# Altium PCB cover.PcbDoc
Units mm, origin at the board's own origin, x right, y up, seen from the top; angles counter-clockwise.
Board outline 100 x 100 mm, 2 copper layers (Top Layer, Bottom Layer); 4 components, 1 nets, 4 pads, 64 vias.
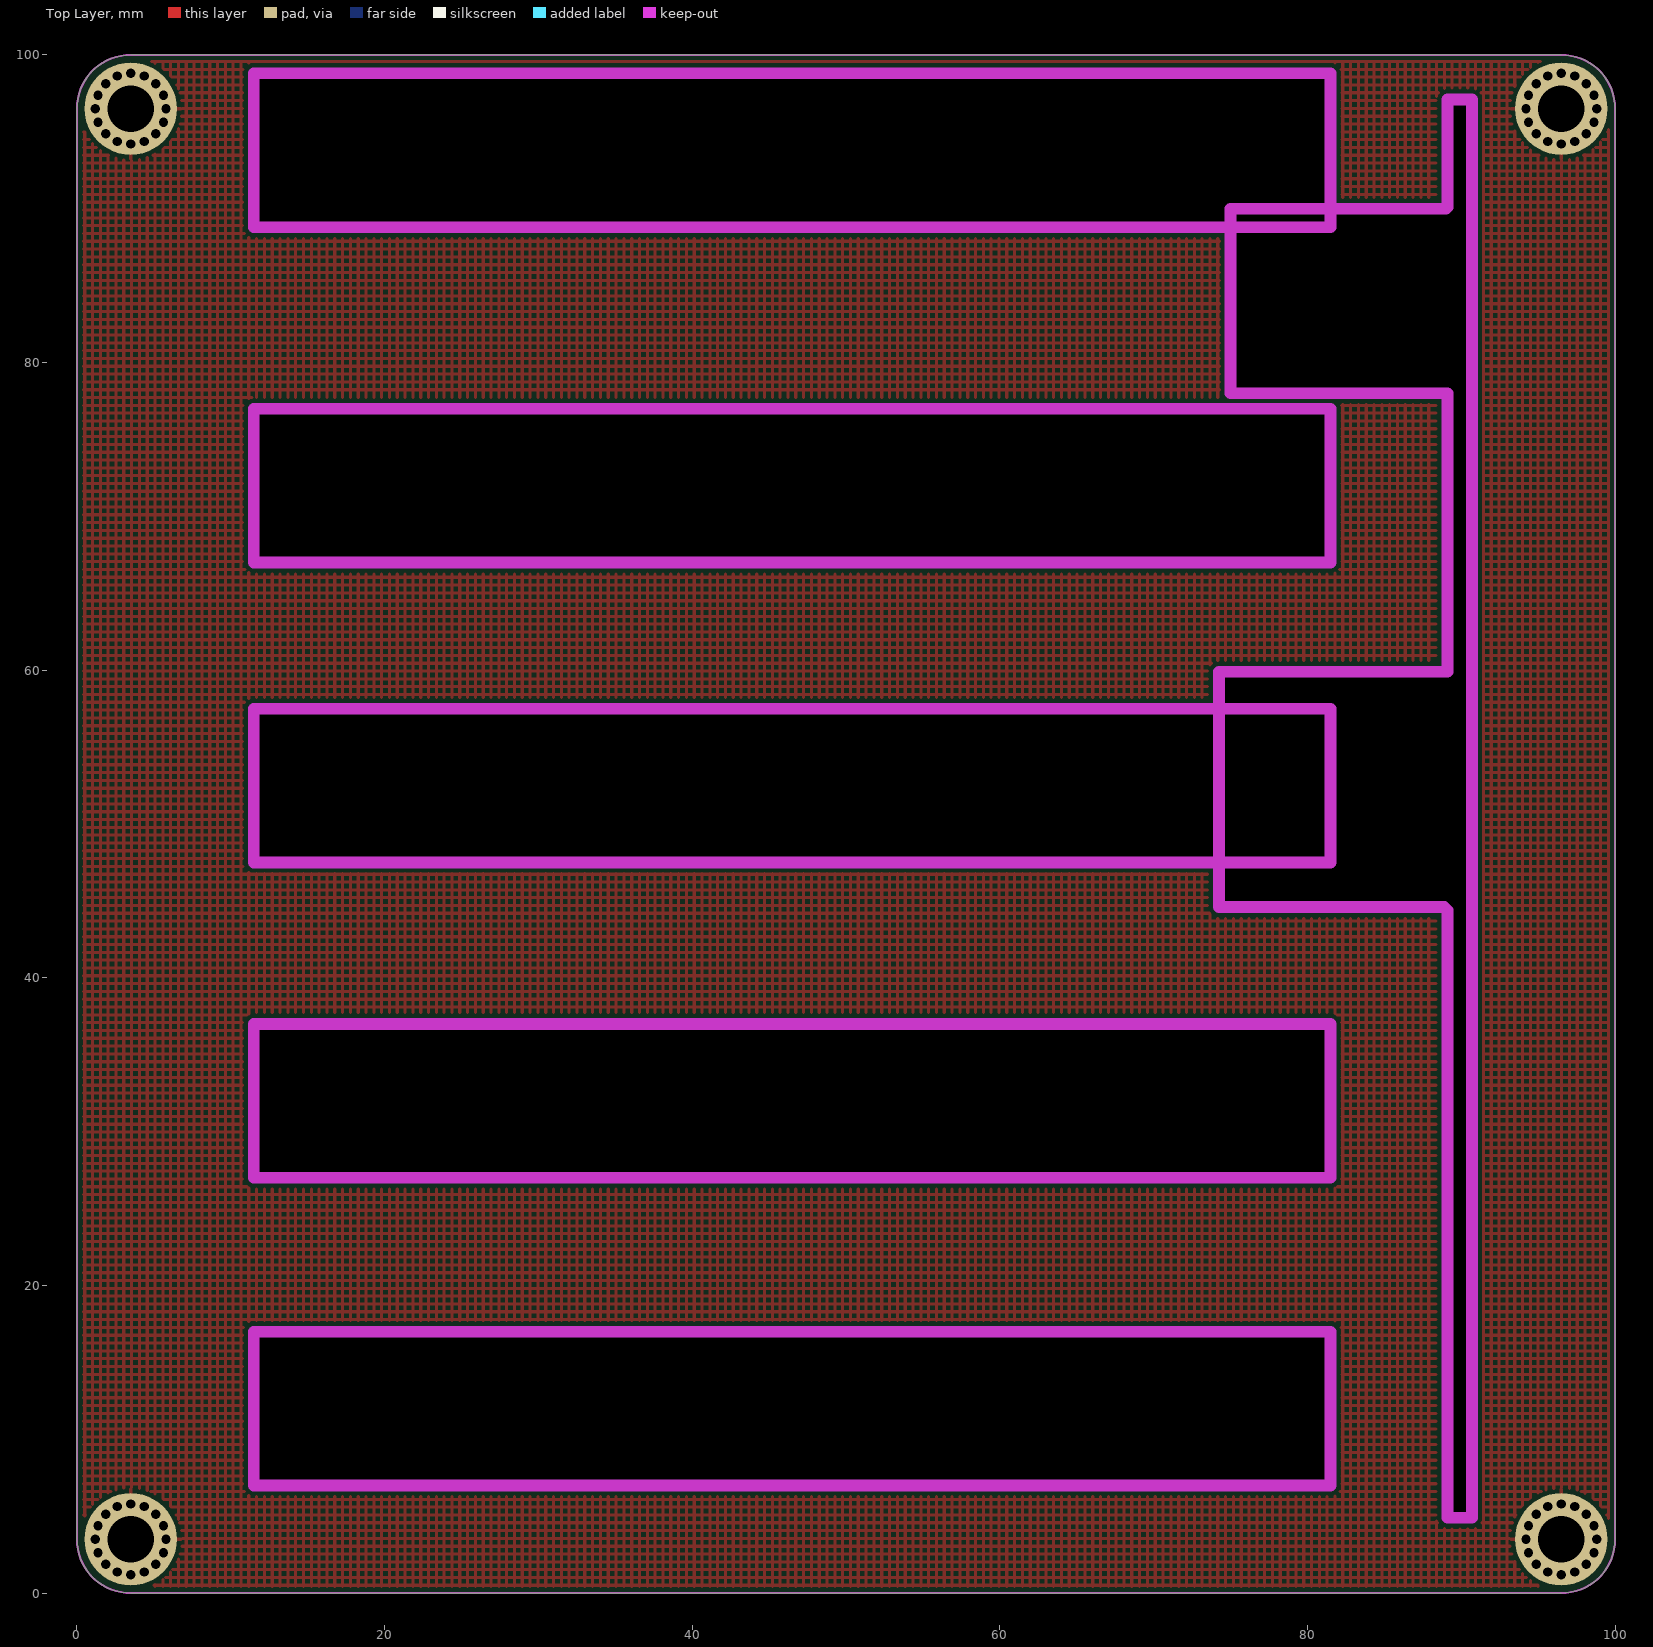
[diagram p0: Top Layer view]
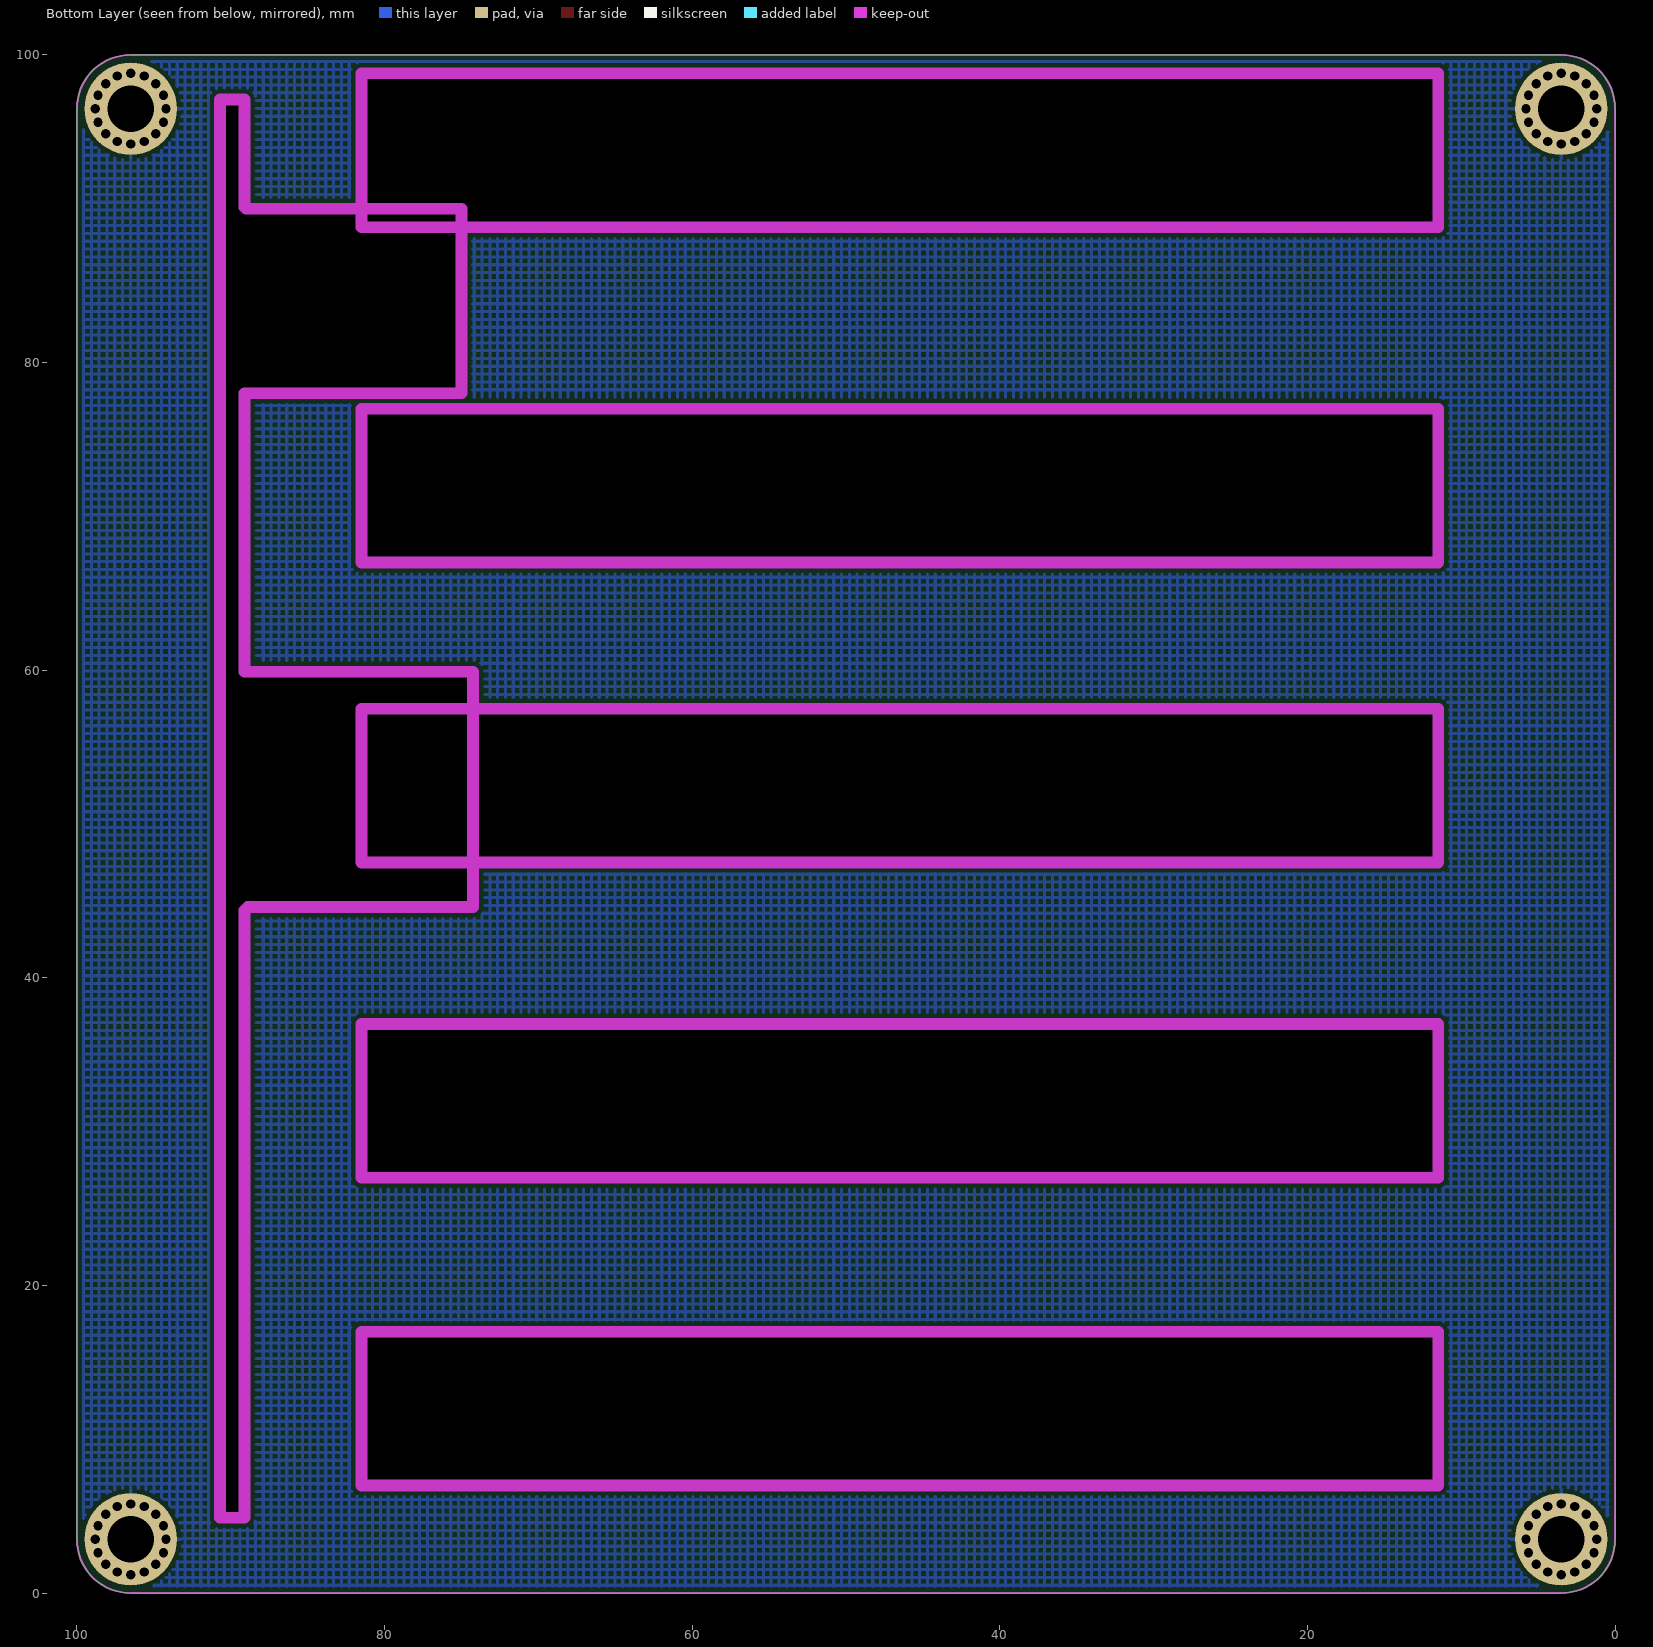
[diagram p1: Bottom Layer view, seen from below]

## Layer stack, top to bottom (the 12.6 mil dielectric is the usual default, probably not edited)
Top Solder: solder mask 0.0102, Solder Resist, Dk 3.5
Top Layer: signal copper 0.0356
Dielectric 1: dielectric 0.32, FR-4, Dk 4.8
Bottom Layer: signal copper 0.0356
Bottom Solder: solder mask 0.0102, Solder Resist, Dk 3.5

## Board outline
0,3.5 0,96.5 cw(c3.5,96.5) 3.5,100 96.5,100 cw(c96.5,96.5) 100,96.5 100,3.5 cw(c96.5,3.5) 96.5,0 3.5,0 cw(c3.5,3.5)
cut-out: 11.5,88.8 81.5,88.8 81.5,98.8 11.5,98.8
cut-out: 11.5,67 81.5,67 81.5,77 11.5,77
cut-out: 11.5,7 81.5,7 81.5,17 11.5,17
cut-out: 11.5,27 81.5,27 81.5,37 11.5,37
cut-out: 11.5,47.5 11.5,57.5 81.5,57.5 81.5,47.5
cut-out: 74.248,44.6 74.248,59.9 89.1,59.9 89.1,78 75,78 75,90 89,90 89.1,90.1 89.1,97.1 90.7,97.1 90.7,4.9 89.1,4.9 89.1,44.4 88.9,44.6

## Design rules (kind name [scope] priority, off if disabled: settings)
Clearance [All] p1: gap=0.254 ignorepadtopadclearanceinfootprint=FALSE except(0: Arc-Hole Track-Hole SMDPad-Hole THPad-Hole Via-Hole Fill-Hole Poly-Hole Region-Hole Text-Hole)
PolygonConnect [All] p1: connectstyle=Relief reliefconductorwidth=0.254 reliefentries=4 polygonreliefangle="90 Angle" airgapwidth=0.254
RoutingVias [All] p1: holewidth=0.711 width=1.27 viastyle="Through Hole" minholewidth=0.3 minwidth=0.6 maxholewidth=100 maxwidth=100
SilkToSilkClearance [All] p1 off: silktosilkclearance=0.254
SilkToSolderMaskClearance [IsPad] p1 off: minsilkscreentomaskgap=0.254 clearancetoexposedcopper=TRUE
SolderMaskExpansion [All] p1: expansion=0.102 istentingtop=FALSE
Width [All] p1: maxlimit=0.254 minlimit=0.254 preferedwidth=0.254
28 further rules are at their usual default settings.

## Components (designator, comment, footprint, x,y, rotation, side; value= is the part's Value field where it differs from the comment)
J1 "M3" M3 3.5,96.5 r0 top
J2 "M3" M3 96.5,96.5 r0 top
J3 "M3" M3 96.5,3.5 r0 top
J4 "M3" M3 3.5,3.5 r0 top

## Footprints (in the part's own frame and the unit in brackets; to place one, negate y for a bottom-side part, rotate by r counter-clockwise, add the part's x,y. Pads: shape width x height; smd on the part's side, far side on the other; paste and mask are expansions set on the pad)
M3 [mm]
  round 6 hole 3: 0(0,0)

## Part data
J1 J2 J3 J4: library part Screw_Hole

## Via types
v1: diameter 0.6, hole 0.6, Top Layer to Bottom Layer, 64 vias

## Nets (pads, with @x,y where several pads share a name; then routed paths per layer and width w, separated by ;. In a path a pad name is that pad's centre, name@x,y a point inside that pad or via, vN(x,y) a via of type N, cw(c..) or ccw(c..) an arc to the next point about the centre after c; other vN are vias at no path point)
GND: J1.0 J2.0 J3.0 J4.0
  other v1: 3.5,1.2 96.5,1.2 2.62,1.375 4.38,1.375 95.62,1.375 97.38,1.375 1.874,1.874 5.126,1.874 94.874,1.874 98.126,1.874 1.375,2.62 5.625,2.62 94.375,2.62 98.625,2.62 1.2,3.5 5.8,3.5 94.2,3.5 98.8,3.5 1.375,4.38 5.625,4.38 94.375,4.38 98.625,4.38 1.874,5.126 5.126,5.126 94.874,5.126 98.126,5.126 2.62,5.625 4.38,5.625 95.62,5.625 97.38,5.625 3.5,5.8 96.5,5.8 3.5,94.2 96.5,94.2 2.62,94.375 4.38,94.375 95.62,94.375 97.38,94.375 1.874,94.874 5.126,94.874 94.874,94.874 98.126,94.874 1.375,95.62 5.625,95.62 94.375,95.62 98.625,95.62 1.2,96.5 5.8,96.5 94.2,96.5 98.8,96.5 1.375,97.38 5.625,97.38 94.375,97.38 98.625,97.38 1.874,98.126 5.126,98.126 94.874,98.126 98.126,98.126 2.62,98.625 4.38,98.625 95.62,98.625 97.38,98.625 3.5,98.8 96.5,98.8

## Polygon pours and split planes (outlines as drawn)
GND on Top Layer "Top Layer-No Net" (hatched 90Degree grid 0.508 track 0.203, remove dead copper, pour order 0): 0,3.5 0,96.5 cw(c3.5,96.5) 3.5,100 96.5,100 cw(c96.5,96.5) 100,96.5 100,3.5 cw(c96.5,3.5) 96.5,0 3.5,0 cw(c3.5,3.5)
GND on Bottom Layer "Top Layer-No Net1" (hatched 90Degree grid 0.508 track 0.203, remove dead copper, pour order 1): 0,3.5 0,96.5 cw(c3.5,96.5) 3.5,100 96.5,100 cw(c96.5,96.5) 100,96.5 100,3.5 cw(c96.5,3.5) 96.5,0 3.5,0 cw(c3.5,3.5)

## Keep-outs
Keep-Out Layer:
  lines w0.127: 0,3.5 ccw(c3.5,3.5) 3.5,0 96.5,0 ccw(c96.5,3.5) 100,3.5 100,96.5 ccw(c96.5,96.5) 96.5,100 3.5,100 ccw(c3.5,96.5) 0,96.5 0,3.5
  lines w0.762: 89,90 75,90 75,78 89.1,78 89.1,59.9 74.248,59.9 74.248,44.6 88.9,44.6 89.1,44.4 89.1,4.9 90.7,4.9 90.7,97.1 89.1,97.1 89.1,90.1 ; 11.5,7 81.5,7 81.5,17 11.5,17 11.5,7 ; 11.5,27 11.5,37 81.5,37 81.5,27 11.5,27 ; 11.5,47.5 11.5,57.5 81.5,57.5 81.5,47.5 11.5,47.5 ; 11.5,67 11.5,77 81.5,77 81.5,67 11.5,67 ; 11.5,88.8 11.5,98.8 81.5,98.8 81.5,88.8 11.5,88.8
